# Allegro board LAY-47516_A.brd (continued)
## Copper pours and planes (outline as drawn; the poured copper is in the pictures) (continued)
GND on TOP (solid shape): 50.09,46.43 50.13,46.41 50.17,46.39 50.31,46.25 50.41,46.18 50.54,46.16 52.7,46.16 52.8,46.05 52.74,45.99 52.7,45.99 52.35,45.63 52.7,45.27 52.76,45.28 52.82,45.29 53.31,45.29 53.31,44.97 53.01,44.97 52.88,44.94 52.77,44.87 51.82,43.91 51.62,44 51.63,44.04 50.52,44.84 50.3,43.49 50.34,43.46 50.26,43.26 39.74,43.26 39.68,43.28 39.62,43.28 39.37,43.18 39.27,42.93 39.27,42.87 39.17,42.75 37.61,42.75 37.51,42.89 37.52,42.92 37.55,43.05 37.56,43.18 37.43,43.65 37.09,44 37.05,44.02 37.11,44.24 37.49,44.24 37.59,44.13 37.59,44.07 37.7,43.8 37.97,43.69 38.06,43.7 38.14,43.73 38.16,43.73 39.12,43.73 39.24,43.76 39.35,43.83 40.61,45.09 40.79,45.04 40.8,45 40.88,44.85 41.01,44.76 41.1,44.71 41.2,44.7 42.96,44.7 42.96,44.65 44.42,44.65 44.42,44.7 44.57,44.7 44.57,43.93 45.34,43.93 45.34,44.7 46.62,44.7 46.68,44.7 47.57,44.7 47.63,44.7 49.1,44.7 49.23,44.73 49.34,44.8 49.9,45.35 49.97,45.46 49.99,45.59 49.99,46.38
GND on TOP (solid shape): outline of 104 points within 51.69,40.98 64.64,51.18
GND on TOP (solid shape): outline of 125 points within 59.62,30.31 84.41,39.75
GND on TOP (solid shape): outline of 106 points within 21.35,48 30.09,51.23
GND on TOP (solid shape): outline of 183 points within 6.43,41.19 18.18,47.72
GND on TOP (solid shape): outline of 930 points within 0.51,34.67 27.89,62.92
GND on TOP (solid shape): outline of 7694 points within 0.51,58.68 104.65,112.39
GND on TOP (solid shape): outline of 13400 points within 0.51,0.51 104.65,66.3
GND on TOP: 0.51,0.51 98.93,0.51 98.93,-30.35 98.81,-30.48 74.3,-30.48 74.17,-30.61 74.17,-34.16 74.3,-34.29 98.93,-34.29 99.06,-34.16 99.06,0.51 104.65,0.51 104.65,112.39 0.51,112.39 ; 3 cut-outs
GND on BOTTOM, L2_GND_1: 0.51,0.51 98.93,0.51 98.93,-30.35 98.81,-30.48 74.3,-30.48 74.17,-30.61 74.17,-34.16 74.3,-34.29 98.93,-34.29 99.06,-34.16 99.06,0.51 104.65,0.51 104.65,112.39 0.51,112.39
VCC_2V0 on TOP: 16.51,75.2 18.07,75.2 18.78,75.91 22.64,75.91 23.11,75.44 23.11,72.77 22.42,72.08 16.95,72.08 16.51,72.52
VCC_2V0 on BOTTOM: 21.13,76.73 17.45,76.73 16.43,75.72 16.43,67.56 14.99,66.12 14.99,58.04 15.49,57.53 18.31,57.53 19,58.22 19,65.86 21.41,68.28 21.41,76.45
VCC_2V0 on L3_PWR_1: 35.31,77.72 17.72,77.72 16.43,76.43 16.43,72.01 33.91,72.01 35.31,73.41
VCC_3V3 on TOP: 16.7,70.35 17.82,70.35 18.37,70.9 23.11,70.9 23.11,67.11 17.3,67.11 16.64,67.76 16.64,70.29
VCC_3V3 on L3_PWR_1: 91.44,88.52 99.95,88.52 100.97,87.5 100.97,71.5 99.06,69.6 97.41,69.6 97.03,69.98 97.03,72.01 96.65,72.39 96.14,72.39 95.76,72.01 95.76,69.98 95.38,69.6 87.12,69.6 87.12,53.47 80.14,46.48 80.14,22.61 79.5,21.97 76.45,21.97 75.69,22.73 75.69,48.77 83.19,56.26 83.19,65.28 81.28,67.18 24.13,67.18 22.99,66.04 22.99,64.14 24.16,62.97 24.16,56.79 21.21,53.85 21.21,48.51 19.18,46.48 8.38,46.48 4.45,42.55 4.45,33.4 5.21,32.64 13.72,32.64 14.61,31.75 14.61,27.69 15.11,27.18 26.03,27.18 26.67,26.54 26.67,20.07 26.03,19.43 25.02,19.43 25.02,21.34 24.51,21.84 5.97,21.84 3.05,24.77 3.05,43.05 7.75,47.75 18.8,47.75 19.94,48.89 19.94,54.61 22.99,57.66 22.99,61.72 21.23,63.47 15.39,63.47 14.99,63.88 14.99,70.69 16.18,71.88 34.42,71.88 38.1,75.56 86.36,75.56 90.68,79.88 90.68,87.76
VCC_3V3_2V0 on L3_PWR_1: 0.51,0.51 98.93,0.51 98.93,-30.35 98.81,-30.48 74.3,-30.48 74.17,-30.61 74.17,-34.16 74.3,-34.29 98.93,-34.29 99.06,-34.16 99.06,0.51 104.65,0.51 104.65,112.39 0.51,112.39
VCC_IF_LINK on BOTTOM: 41.66,89.92 31.24,89.92 31.24,72.77 36.2,67.82 36.2,65.41 36.45,65.15 39.5,65.15 39.62,65.28 39.62,83.31 41.66,83.31
(no net) on TOP: 1.15,67.06 4.4,67.06 5.59,65.87 5.59,63.48 3.93,63.47 3.47,63.01 3.47,60.07 3.58,59.96 5.23,59.96 5.23,59.64 5.46,59.41 5.46,57.53 5.84,57.15 6.97,57.15 7.14,56.98 7.14,55.99 6.94,55.78 3.94,55.78 0.64,55.78 0.64,66.54
FL_2V5 on TOP: 28.09,61.8 33.3,61.8 33.76,61.34 33.75,60.18 33.52,59.95 30.99,59.95 30.54,59.49 30.54,57.15 31.24,57.15 31.5,56.9 31.5,53.59 30.86,52.96 19.94,52.96 18.87,54.03 18.87,56.34 19.08,56.54 26.26,56.54 26.69,56.97 26.7,58.55 27.58,59.44 27.58,61.29
FL_2V5 on BOTTOM: 30.73,53.85 30.73,57.66 28.32,60.07 28.32,89.41 27.3,90.42 23.62,90.42 22.99,89.79 22.99,56.77 26.42,53.34 30.23,53.34
FL_2V5 on L3_PWR_1: 5.46,32.89 4.7,33.66 4.7,42.55 8.38,46.23 19.18,46.23 20.83,47.88 20.83,53.85 24.65,57.67 30.62,57.67 31.24,57.05 31.24,53.77 30.13,52.67 25.37,52.67 25.17,52.48 25.17,49.25 25.78,48.64 25.78,33.02 22.58,29.82 16.54,29.82 15.72,29.01 15.72,27.69 14.78,27.69 14.48,27.99 14.48,31.75 13.34,32.89
FL_2V5 on L3_PWR_1: 19.05,56.64 20.7,56.64 20.83,56.52 20.83,55.8 19.74,54.71 19.74,48.97 18.64,47.88 7.57,47.88 2.79,43.1 2.79,24.64 5.84,21.59 20.57,21.59 21.16,21.01 21.16,12.85 19.63,11.33 4.04,11.33 1.4,13.97 1.4,43.48 6.78,48.87 18.14,48.87 18.85,49.58 18.85,56.41 19.05,56.62
FL_USB_5V0 on TOP: 5.33,69.6 5.33,67.56 6.99,67.56 11.43,63.12 26.94,63.12 28.03,62.03 33.96,62.03 34.32,62.38 34.32,66.52 33.81,67.03 9.91,67.03 8.89,68.05 8.89,69.6
MCU_VDD on L3_PWR_1: 72.01,54.99 72.01,36.47 52.45,36.47 52.45,48.26 56.77,52.58 68.45,52.58 68.45,57.78 69.72,59.05 79.76,59.05 80.39,58.42 80.39,56.52 79.76,55.88 72.9,55.88
SYS_5V0 on TOP: 9.1,68.15 9.1,69.85 5.08,69.85 4.95,69.72 4.95,67.82 4.57,67.44 2.67,67.44 2.41,67.69 2.41,77.72 4.57,79.88 18.63,79.88 18.63,76.03 17.91,75.31 15.88,75.31 15.88,71.88 17.99,71.88 17.99,70.87 17.64,70.53 16.59,70.53 16.47,70.64 16.47,71.32 16.36,71.43 14.79,71.43 14.67,71.32 14.67,70.6 14.54,70.47 12.55,70.47 12.21,70.12 12.21,69.54 12.55,69.19 14.65,69.19 14.67,69.22 14.67,67.72 14.35,67.39 9.86,67.39
SYS_5V0 on BOTTOM: 9.14,77.72 15.2,77.72 15.2,71.13 14.61,70.53 14.61,57.91 8.38,51.69 4.32,51.69 3.89,52.12 3.89,54.05 11.56,61.72 11.56,64.64 9.14,67.06
SYS_5V0 on L3_PWR_1: 4.7,52.7 6.35,52.7 6.48,52.58 6.48,48.89 1.4,43.81 1.4,13.72 4.06,11.05 27.18,11.05 32.13,6.1 40.13,6.1 40.77,6.73 40.77,28.7 40.13,29.34 36.07,29.34 35.43,29.97 35.43,33.78 35.94,34.29 45.21,34.29 46.86,32.64 46.86,2.41 17.4,2.41 11.3,8.51 2.03,8.51 0.51,10.03 0.51,44.58 4.57,48.64 4.57,52.58
SYS_5V0 on L3_PWR_1: 54.36,104.39 54.36,91.69 53.59,90.93 45.97,90.93 45.34,91.57 45.34,93.6 45.72,93.98 48.46,93.98 50.04,95.55 50.04,97.79 40.13,97.79 40.13,92.71 36.07,92.71 36.07,83.69 30.35,77.98 17.65,77.98 16.26,76.58 16.26,72.26 14.73,70.74 14.73,67.79 10.29,67.79 9.91,68.17 9.91,83.36 11.89,85.34 16.13,85.34 16.13,82.42 16.64,81.91 18.54,81.91 19.05,82.42 19.05,85.34 24.77,85.34 29.84,90.42 29.84,104.39
N00831 on TOP (solid shape): 5.59,65.87 5.59,63.48 5.25,63.48 5.16,63.64 5.18,63.67 5.25,63.84 5.28,64.02 5.09,64.48 4.63,64.67 4.42,64.67 3.97,64.48 3.78,64.02 3.82,63.78 3.95,63.58 3.99,63.53 3.69,63.22 3.53,63.22 3.53,65.34 2.61,65.34 2.61,65.79 2.42,66.24 1.98,66.42 1.08,66.42 0.94,66.41 0.82,66.37 0.79,66.35 0.64,66.45 0.64,66.54 1.15,67.06 4.4,67.06
N00831 on TOP (solid shape): 4.09,59.93 4.11,59.74 4.07,59.71 3.85,59.48 3.78,59.17 3.97,58.71 4.42,58.52 4.63,58.52 5.09,58.71 5.28,59.17 5.25,59.35 5.18,59.52 5.15,59.56 5.23,59.64 5.46,59.41 5.46,57.53 5.84,57.15 6.01,57.15 6.01,56.35 7.14,56.35 7.14,55.99 6.94,55.78 3.94,55.78 0.64,55.78 0.64,56.74 0.79,56.83 0.82,56.82 0.94,56.78 1.08,56.76 1.98,56.76 2.42,56.95 2.61,57.39 2.61,57.84 3.53,57.84 3.53,59.96 4.01,59.96
N00831 on BOTTOM: 0.97,66.87 4.59,66.87 5.42,66.04 5.42,63.2 3.47,63.19 3.47,60.07 3.58,59.96 5.11,59.96 5.46,59.61 5.46,58.55 3.56,56.64 0.64,56.64 0.64,66.54
N10980 on TOP: 21.08,31.95 20.37,31.95 18.31,34.01 18.31,35.41 18.99,36.08 21.26,36.08 21.26,32.18 21.06,31.98
N10980 on BOTTOM: 12.4,37.44 19.33,37.44 19.96,36.8 19.96,32.77 16.69,32.77 16.46,32.99 16.46,34.67 15.79,35.34 12.56,35.34 12.4,35.51 ; 1 cut-out

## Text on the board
BOTTOM: 07 | L4_SS | 170-47516 REV A
Board Geometry/Soldermask Bottom: 08 | SECONDARY SOLDERMASK
Ref Des/Silkscreen Bottom: 09 | SECONDARY SILKSCREEN
User.Comments: 1 OF 1 | TEST PROBE | 1/1 | 1
TOP: 04 | L1_PS
Board Geometry/Soldermask Top: 03 | PRIMARY SOLDERMASK
Ref Des/Silkscreen Top: 2V0 | nRST | GND | +3V3 | A0 | A1 | A2 | A3 | A4 | A5 | +5V | Vin | PWM | INT | SDA | SCL | RX | TX | MISO | MOSI | RST | AN | SCK | CS | AVDD | D15 | D14 | D7 | D6 | D5 | D4 | D3 | D2 | D1 | D0 | D8 | D13 | D12 | D11 | D10 | D9 | CAN | USB | 3V3 | 02 | PRIMARY SILKSCREEN | LPCXpresso55S06 | LPC55S06-EVK | H | L
L2_GND_1: 05 | L2_GND_1
L3_PWR_1: 06 | L3_PWR_1
XSECTION_CHART: *  SURFACE - AIR 0 MIL(+0/-0) | *  DIELECTRIC - DRY_FILM_MASK 0.8 MIL(+0/-0) | L1 TOP CONDUCTOR - 1OZ_COPPER 1.4 MIL(+0/-0) | *  DIELECTRIC - FR-4 4.15 MIL(+0/-0) | L2 L2_GND_1 PLANE - 1OZ_COPPER 1.25 MIL(+0/-0) | *  DIELECTRIC - FR-4 IT180 44.5 MIL(+0/-0) | L3 L3_PWR_1 PLANE - 1OZ_COPPER 1.25 MIL(+0/-0) | L4 BOTTOM CONDUCTOR - 1OZ_COPPER 1.4 MIL(+0/-0) | DESIGN CROSS SECTION CHART | ___________________________ | TOTAL THICKNESS 59.7 MIL | 1-4
DIMENSION: BOARD THICKNESS TOLERANCE +/-10% | 8 | A.  HOLES TO BE OPTICALLY DRILLED AT SECONDARY DRILL STEP REFERENCING THE SECONDARY DATUM. | ALL HOLE LOCATION TOLERANCES ARE TO BE +/-.001 IN REFERENCE TO THE SECONDARY DATUM. | 19A | 19 | 16 | DETAIL | LAYER STACKUP | SCALE: NONE | SOCKET U28 PIN 1 | SECONDATY DATUM | PRIMARY DATUM | GRID ORIGIN | A
DISPLAY_TOP: 01 | PRIMARY PASTEMASK
User.5: 10 | SECONDARY PASTEMASK
User.10: OF 10
User.13: 22. THIS FAB_VIAFILL.ART SHOWS LOCATIONS OF VIA-IN-PAD TO BE FILLED. | 1/1 | 2 | 3 | FAB SUPPLIER: DISREGARD THIS PAGE IF VIA-IN-PAD DOESN'T APPLY OR NOT REQUIRED ON FAB.ART | CAD DESIGNER: DELETE THIS FAB PAGE IF VIAL FILL IS NOT USED ON THIS DESIGN
User.14: 24. | 1/1 | 3 | CAD DESIGNER: DELETE THIS FAB PAGE IF BACKDRILL IS NOT USED ON THIS DESIGN. | FAB SUPPLIER: DISREGARD THIS PAGE IF BACKDRILL REQUIRMENT IS NOT PROVIDED.
User.18: 6.5 | 50 | 5.5 | 90
User.19: TOP TO LAYER X | BACK DRILL REFERENCE | BOTTOM TO LAYER X | LAYER X | MUST CUT LAYER | LAYER X+1 | MUST NOT CUT LAYER | LAYER X-1
User.21: FIGURE | FINISHED_SIZE | 8.0 | 10.0 | 26.0 | 40.0 | 43.0 | 47.0 | 126.0 | 139.0 | 33.0 | 67.0 | 33.0x26.0 | 59.0x32.0 | DRILL CHART: TOP to BOTTOM | ALL UNITS ARE IN MILS | TOLERANCE_DRILL | +0.0/-8.0 | +0.0/-10.0 | +2.0/-2.0 | +3.0/-3.0 | +1.0/-1.0 | +4.0/-4.0 | PLATED | NON-PLATED | QTY | 346 | 230 | 20 | 162 | 4 | 9 | 2
